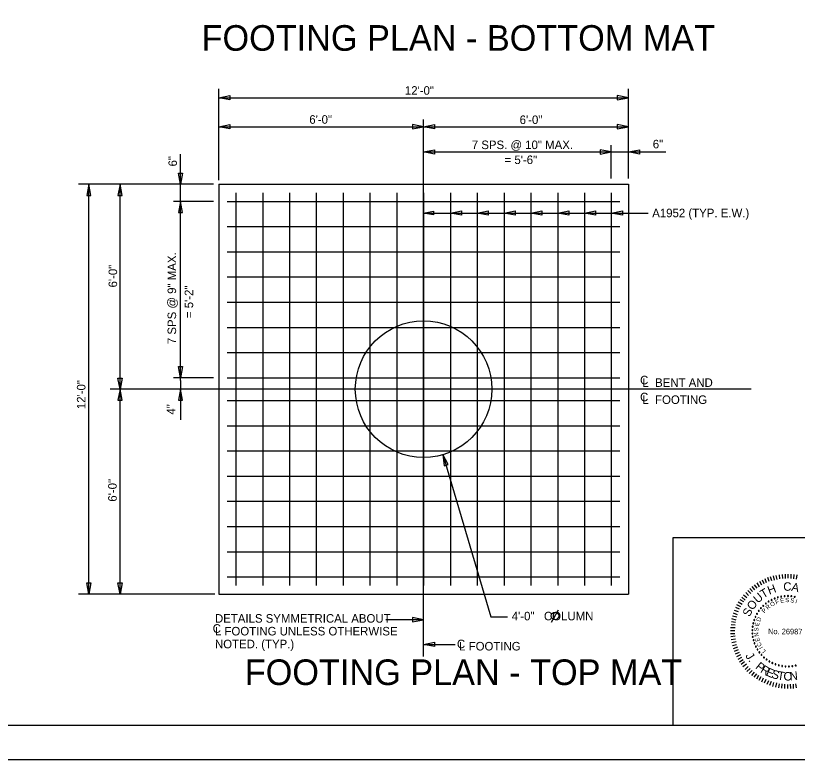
# Model space of a CAD drawing. Extents: x 1970675.2 to 1970711.3, y 796145.2 to 796167.2.
# Drawn here: x 1970688.24 to 1970699.69, y 796145.25 to 796156.14 of the extents above; entities that cross this region are included whole.
import ezdxf

# ---------------------------------------------------------------- set-up
doc = ezdxf.new("R2010")
doc.units = 0
for name, color, linetype in [('BR_AUTO DIMENSION', 7, 'Continuous'), ('BR_BORDER LINES', 7, 'Continuous'), ('BR_CENTER LINES', 7, 'Continuous'), ('BR_CONCRETE', 7, 'Continuous'), ('BR_REBAR', 7, 'Continuous'), ('BR_TEXT', 7, 'Continuous'), ('Level 31', 7, 'Continuous')]:
    doc.layers.add(name, color=color, linetype=linetype)

msp = doc.modelspace()

# ---------------------------------------------------------------- linework, layer by layer
at = {"layer": 'BR_AUTO DIMENSION'}
for p, q in [((1970691.212, 796153.727), (1970691.212, 796155.064)), ((1970697.212, 796153.753), (1970697.212, 796155.064)), ((1970691.212, 796154.935), (1970697.212, 796154.935)), ((1970691.212, 796154.511), (1970694.212, 796154.511)), ((1970694.212, 796154.511), (1970697.212, 796154.511)), ((1970696.962, 796153.753), (1970696.962, 796154.239)), ((1970690.652, 796153.182), (1970690.652, 796154.11)), ((1970694.212, 796154.142), (1970697.761, 796154.142)), ((1970691.134, 796153.667), (1970689.155, 796153.667)), ((1970689.308, 796147.667), (1970689.308, 796153.667)), ((1970689.766, 796150.667), (1970689.766, 796153.667)), ((1970691.134, 796153.417), (1970690.551, 796153.417)), ((1970690.652, 796150.792), (1970690.652, 796153.417)), ((1970694.212, 796153.246), (1970697.5, 796153.246)), ((1970691.134, 796150.834), (1970690.551, 796150.834)), ((1970690.652, 796150.792), (1970690.652, 796150.219)), ((1970689.766, 796147.667), (1970689.766, 796150.667)), ((1970694.496, 796149.709), (1970695.199, 796147.333)), ((1970691.152, 796147.667), (1970689.155, 796147.667)), ((1970695.199, 796147.333), (1970695.443, 796147.333)), ((1970694.212, 796147.291), (1970693.66, 796147.291)), ((1970694.212, 796146.93), (1970694.673, 796146.93))]:
    msp.add_line(p, q, dxfattribs=at)
for points in [[(1970691.374, 796154.904), (1970691.212, 796154.935), (1970691.374, 796154.966)], [(1970697.049, 796154.904), (1970697.212, 796154.935), (1970697.049, 796154.966)], [(1970691.374, 796154.48), (1970691.212, 796154.511), (1970691.374, 796154.543)], [(1970694.049, 796154.48), (1970694.212, 796154.511), (1970694.049, 796154.543)], [(1970694.374, 796154.48), (1970694.212, 796154.511), (1970694.374, 796154.543)], [(1970697.049, 796154.48), (1970697.212, 796154.511), (1970697.049, 796154.543)], [(1970694.374, 796154.111), (1970694.212, 796154.142), (1970694.374, 796154.173)], [(1970696.799, 796154.111), (1970696.962, 796154.142), (1970696.799, 796154.173)], [(1970697.374, 796154.111), (1970697.212, 796154.142), (1970697.374, 796154.173)], [(1970690.683, 796153.83), (1970690.652, 796153.667), (1970690.62, 796153.83)], [(1970689.339, 796153.505), (1970689.308, 796153.667), (1970689.277, 796153.505)], [(1970689.797, 796153.505), (1970689.766, 796153.667), (1970689.735, 796153.505)], [(1970690.683, 796153.255), (1970690.652, 796153.417), (1970690.62, 796153.255)], [(1970694.358, 796153.218), (1970694.212, 796153.246), (1970694.358, 796153.275)], [(1970694.767, 796153.215), (1970694.605, 796153.246), (1970694.767, 796153.278)], [(1970695.16, 796153.215), (1970694.998, 796153.246), (1970695.16, 796153.278)], [(1970695.553, 796153.215), (1970695.39, 796153.246), (1970695.553, 796153.278)], [(1970695.946, 796153.215), (1970695.783, 796153.246), (1970695.946, 796153.278)], [(1970696.339, 796153.215), (1970696.176, 796153.246), (1970696.339, 796153.278)], [(1970696.731, 796153.215), (1970696.569, 796153.246), (1970696.731, 796153.278)], [(1970697.124, 796153.215), (1970696.962, 796153.246), (1970697.124, 796153.278)], [(1970690.683, 796150.997), (1970690.652, 796150.834), (1970690.62, 796150.997)], [(1970689.797, 796150.83), (1970689.766, 796150.667), (1970689.735, 796150.83)], [(1970689.797, 796150.505), (1970689.766, 796150.667), (1970689.735, 796150.505)], [(1970690.683, 796150.505), (1970690.652, 796150.667), (1970690.62, 796150.505)], [(1970694.572, 796149.562), (1970694.496, 796149.709), (1970694.512, 796149.544)], [(1970689.339, 796147.83), (1970689.308, 796147.667), (1970689.277, 796147.83)], [(1970689.797, 796147.83), (1970689.766, 796147.667), (1970689.735, 796147.83)], [(1970694.049, 796147.26), (1970694.212, 796147.291), (1970694.049, 796147.322)], [(1970694.374, 796146.899), (1970694.212, 796146.93), (1970694.374, 796146.961)]]:
    msp.add_lwpolyline(points, close=True, dxfattribs=at)
at = {"layer": 'BR_BORDER LINES'}
for p, q in [((1970697.87, 796148.496), (1970703.236, 796148.496)), ((1970697.87, 796145.746), (1970697.87, 796148.496)), ((1970677.07, 796145.746), (1970710.736, 796145.746))]:
    msp.add_line(p, q, dxfattribs=at)
at = {"layer": 'BR_CENTER LINES'}
for p, q in [((1970694.212, 796146.752), (1970694.212, 796154.617)), ((1970699.009, 796150.667), (1970689.62, 796150.667))]:
    msp.add_line(p, q, dxfattribs=at)
at = {"layer": 'BR_CONCRETE'}
for p, q in [((1970691.212, 796153.667), (1970697.212, 796153.667)), ((1970691.212, 796153.667), (1970691.212, 796147.667)), ((1970697.212, 796153.667), (1970697.212, 796147.667)), ((1970691.212, 796147.667), (1970697.212, 796147.667))]:
    msp.add_line(p, q, dxfattribs=at)
msp.add_circle((1970694.212, 796150.667), 1, dxfattribs=at)
at = {"layer": 'BR_REBAR'}
for p, q in [((1970691.462, 796153.542), (1970691.462, 796147.792)), ((1970691.855, 796153.542), (1970691.855, 796147.792)), ((1970692.248, 796153.542), (1970692.248, 796147.792)), ((1970692.64, 796153.542), (1970692.64, 796147.792)), ((1970693.033, 796153.542), (1970693.033, 796147.792)), ((1970693.426, 796153.542), (1970693.426, 796147.792)), ((1970693.819, 796153.542), (1970693.819, 796147.792)), ((1970694.212, 796153.542), (1970694.212, 796147.792)), ((1970694.605, 796153.542), (1970694.605, 796147.792)), ((1970694.998, 796153.542), (1970694.998, 796147.792)), ((1970695.39, 796153.542), (1970695.39, 796147.792)), ((1970695.783, 796153.542), (1970695.783, 796147.792)), ((1970696.176, 796153.542), (1970696.176, 796147.792)), ((1970696.569, 796153.542), (1970696.569, 796147.792)), ((1970696.962, 796153.542), (1970696.962, 796147.792)), ((1970691.337, 796153.417), (1970697.087, 796153.417)), ((1970691.337, 796153.048), (1970697.087, 796153.048)), ((1970691.337, 796152.679), (1970697.087, 796152.679)), ((1970691.337, 796152.31), (1970697.087, 796152.31)), ((1970691.337, 796151.941), (1970697.087, 796151.941)), ((1970691.337, 796151.572), (1970697.087, 796151.572)), ((1970691.337, 796151.203), (1970697.087, 796151.203)), ((1970691.337, 796150.834), (1970697.087, 796150.834)), ((1970691.337, 796150.501), (1970697.087, 796150.501)), ((1970691.337, 796150.132), (1970697.087, 796150.132)), ((1970691.337, 796149.763), (1970697.087, 796149.763)), ((1970691.337, 796149.394), (1970697.087, 796149.394)), ((1970691.337, 796149.025), (1970697.087, 796149.025)), ((1970691.337, 796148.656), (1970697.087, 796148.656)), ((1970691.337, 796148.287), (1970697.087, 796148.287)), ((1970691.337, 796147.917), (1970697.087, 796147.917))]:
    msp.add_line(p, q, dxfattribs=at)
at = {"layer": 'BR_TEXT'}
for p, q in [((1970699.237, 796147.833), (1970699.213, 796147.889)), ((1970699.275, 796147.85), (1970699.255, 796147.908)), ((1970699.315, 796147.862), (1970699.293, 796147.92)), ((1970699.351, 796147.872), (1970699.338, 796147.933)), ((1970699.392, 796147.882), (1970699.378, 796147.941)), ((1970699.432, 796147.889), (1970699.423, 796147.95)), ((1970699.472, 796147.893), (1970699.468, 796147.954)), ((1970699.511, 796147.896), (1970699.512, 796147.96)), ((1970699.553, 796147.898), (1970699.554, 796147.96)), ((1970699.595, 796147.895), (1970699.597, 796147.959)), ((1970699.635, 796147.892), (1970699.64, 796147.953)), ((1970699.674, 796147.887), (1970699.685, 796147.948)), ((1970699.065, 796147.728), (1970699.025, 796147.778)), ((1970699.099, 796147.753), (1970699.06, 796147.804)), ((1970699.13, 796147.774), (1970699.099, 796147.829)), ((1970699.165, 796147.798), (1970699.135, 796147.852)), ((1970699.2, 796147.816), (1970699.174, 796147.872)), ((1970698.973, 796147.645), (1970698.93, 796147.688)), ((1970699.003, 796147.676), (1970698.959, 796147.72)), ((1970699.032, 796147.703), (1970698.991, 796147.748)), ((1970698.876, 796147.515), (1970698.822, 796147.547)), ((1970698.901, 796147.551), (1970698.847, 796147.584)), ((1970698.922, 796147.58), (1970698.873, 796147.62)), ((1970698.948, 796147.614), (1970698.899, 796147.653)), ((1970696.084, 796147.256), (1970696.189, 796147.438)), ((1970698.824, 796147.405), (1970698.766, 796147.427)), ((1970698.841, 796147.444), (1970698.784, 796147.469)), ((1970698.859, 796147.481), (1970698.802, 796147.508)), ((1970698.799, 796147.329), (1970698.738, 796147.344)), ((1970698.812, 796147.365), (1970698.75, 796147.388)), ((1970698.777, 796147.21), (1970698.715, 796147.217)), ((1970698.781, 796147.251), (1970698.721, 796147.259)), ((1970698.792, 796147.287), (1970698.729, 796147.303)), ((1970698.774, 796147.171), (1970698.709, 796147.171)), ((1970698.772, 796147.129), (1970698.709, 796147.13)), ((1970698.773, 796147.086), (1970698.709, 796147.085)), ((1970698.775, 796147.048), (1970698.714, 796147.041)), ((1970698.779, 796147.007), (1970698.718, 796146.998)), ((1970698.789, 796146.967), (1970698.727, 796146.954)), ((1970698.796, 796146.925), (1970698.735, 796146.911)), ((1970698.808, 796146.888), (1970698.746, 796146.867)), ((1970698.819, 796146.849), (1970698.761, 796146.828)), ((1970698.836, 796146.812), (1970698.778, 796146.785)), ((1970698.853, 796146.776), (1970698.796, 796146.746)), ((1970698.87, 796146.739), (1970698.816, 796146.708)), ((1970698.894, 796146.702), (1970698.839, 796146.671)), ((1970698.915, 796146.673), (1970698.865, 796146.636)), ((1970698.94, 796146.639), (1970698.89, 796146.6)), ((1970698.965, 796146.605), (1970698.921, 796146.564)), ((1970698.994, 796146.579), (1970698.949, 796146.534)), ((1970699.023, 796146.549), (1970698.98, 796146.503)), ((1970699.055, 796146.523), (1970699.014, 796146.476)), ((1970699.088, 796146.497), (1970699.049, 796146.449)), ((1970699.119, 796146.475), (1970699.088, 796146.423)), ((1970699.154, 796146.453), (1970699.123, 796146.399)), ((1970699.188, 796146.433), (1970699.161, 796146.377)), ((1970699.225, 796146.415), (1970699.201, 796146.36)), ((1970699.263, 796146.398), (1970699.242, 796146.341)), ((1970699.303, 796146.385), (1970699.28, 796146.327)), ((1970699.339, 796146.373), (1970699.325, 796146.314)), ((1970699.38, 796146.366), (1970699.365, 796146.304)), ((1970699.419, 796146.354), (1970699.409, 796146.296)), ((1970699.459, 796146.35), (1970699.454, 796146.288)), ((1970699.498, 796146.347), (1970699.498, 796146.285)), ((1970699.54, 796146.344), (1970699.54, 796146.283)), ((1970699.582, 796146.346), (1970699.584, 796146.284)), ((1970699.623, 796146.348), (1970699.626, 796146.286)), ((1970699.661, 796146.352), (1970699.671, 796146.294))]:
    msp.add_line(p, q, dxfattribs=at)
msp.add_circle((1970696.137, 796147.347), 0.055, dxfattribs=at)
for centre, start, end in [((1970699.265, 796147.557), 32.7576, 212.7576), ((1970699.265, 796147.557), 212.7576, 32.7576), ((1970699.309, 796147.581), 27.2191, 207.2191), ((1970699.309, 796147.581), 207.2191, 27.2191), ((1970699.354, 796147.602), 21.6807, 201.6807), ((1970699.354, 796147.602), 201.6807, 21.6807), ((1970699.401, 796147.618), 16.1422, 196.1422), ((1970699.401, 796147.618), 196.1422, 16.1422), ((1970699.45, 796147.629), 10.6038, 190.6038), ((1970699.45, 796147.629), 190.6038, 10.6038), ((1970699.499, 796147.636), 5.0653, 185.0653), ((1970699.499, 796147.636), 185.0653, 5.0653), ((1970699.549, 796147.638), 359.5268, 179.5268), ((1970699.549, 796147.638), 179.5268, 359.5268), ((1970699.599, 796147.635), 353.9884, 173.9884), ((1970699.599, 796147.635), 173.9884, 353.9884), ((1970699.648, 796147.627), 348.4499, 168.4499), ((1970699.648, 796147.627), 168.4499, 348.4499), ((1970699.153, 796147.459), 49.373, 229.373), ((1970699.153, 796147.459), 229.373, 49.373), ((1970699.187, 796147.495), 43.8345, 223.8345), ((1970699.187, 796147.495), 223.8345, 43.8345), ((1970699.225, 796147.528), 38.2961, 218.2961), ((1970699.225, 796147.528), 218.2961, 38.2961), ((1970699.073, 796147.333), 65.9884, 245.9884), ((1970699.073, 796147.333), 245.9884, 65.9884), ((1970699.095, 796147.378), 60.4499, 240.4499), ((1970699.095, 796147.378), 240.4499, 60.4499), ((1970699.122, 796147.42), 54.9114, 234.9114), ((1970699.122, 796147.42), 234.9114, 54.9114), ((1970699.041, 796147.239), 77.0653, 257.0653), ((1970699.041, 796147.239), 257.0653, 77.0653), ((1970699.055, 796147.287), 71.5268, 251.5268), ((1970699.055, 796147.287), 251.5268, 71.5268), ((1970699.028, 796147.14), 88.1422, 268.1422), ((1970699.029, 796147.09), 93.6807, 273.6807), ((1970699.032, 796147.19), 82.6038, 262.6038), ((1970699.028, 796147.14), 268.1422, 88.1422), ((1970699.029, 796147.09), 273.6807, 93.6807), ((1970699.032, 796147.19), 262.6038, 82.6038), ((1970699.034, 796147.041), 99.2191, 279.2191), ((1970699.034, 796147.041), 279.2191, 99.2191), ((1970699.045, 796146.992), 104.7576, 284.7576), ((1970699.045, 796146.992), 284.7576, 104.7576), ((1970699.059, 796146.944), 110.2961, 290.2961), ((1970699.059, 796146.944), 290.2961, 110.2961), ((1970699.079, 796146.898), 115.8345, 295.8345), ((1970699.079, 796146.898), 295.8345, 115.8345), ((1970699.103, 796146.855), 121.373, 301.373), ((1970699.103, 796146.855), 301.373, 121.373), ((1970699.131, 796146.813), 126.9114, 306.9114), ((1970699.131, 796146.813), 306.9114, 126.9114), ((1970699.162, 796146.775), 132.4499, 312.4499), ((1970699.162, 796146.775), 312.4499, 132.4499), ((1970699.198, 796146.74), 137.9884, 317.9884), ((1970699.198, 796146.74), 317.9884, 137.9884), ((1970699.236, 796146.708), 143.5268, 323.5268), ((1970699.236, 796146.708), 323.5268, 143.5268), ((1970699.278, 796146.68), 149.0653, 329.0653), ((1970699.278, 796146.68), 329.0653, 149.0653), ((1970699.321, 796146.657), 154.6038, 334.6038), ((1970699.321, 796146.657), 334.6038, 154.6038), ((1970699.367, 796146.638), 160.1422, 340.1422), ((1970699.367, 796146.638), 340.1422, 160.1422), ((1970699.415, 796146.623), 345.6807, 165.6807), ((1970699.662, 796146.62), 13.373, 193.373), ((1970699.415, 796146.623), 165.6807, 345.6807), ((1970699.464, 796146.613), 351.2191, 171.2191), ((1970699.464, 796146.613), 171.2191, 351.2191), ((1970699.513, 796146.607), 356.7576, 176.7576), ((1970699.513, 796146.607), 176.7576, 356.7576), ((1970699.563, 796146.607), 2.2961, 182.2961), ((1970699.563, 796146.607), 182.2961, 2.2961), ((1970699.613, 796146.611), 7.8345, 187.8345), ((1970699.613, 796146.611), 187.8345, 7.8345), ((1970699.662, 796146.62), 193.373, 13.373)]:
    msp.add_arc(centre, 0.00701, start, end, dxfattribs=at)
at = {"layer": 'Level 31'}
msp.add_lwpolyline([(1970675.236, 796167.246), (1970675.236, 796145.246), (1970711.236, 796145.246), (1970711.236, 796167.246)], dxfattribs=at)

# ---------------------------------------------------------------- texts
at = {"layer": 'BR_AUTO DIMENSION'}
for s, p in [('12\'-0"', (1970693.938, 796154.979)), ('6\'-0"', (1970692.538, 796154.554)), ('6\'-0"', (1970695.619, 796154.55)), ('C', (1970697.383, 796150.738)), ('C', (1970697.383, 796150.49)), ('C', (1970691.123, 796147.1)), ('C', (1970694.7, 796146.874))]:
    msp.add_text(s, height=0.125, dxfattribs=at).set_placement(p)
for s, p in [('6\'-0"', (1970689.723, 796152.157)), ('12\'-0"', (1970689.259, 796150.375)), ('6\'-0"', (1970689.717, 796149.02))]:
    msp.add_text(s, height=0.125, rotation=90, dxfattribs=at).set_placement(p)
at = {"layer": 'BR_TEXT'}
for s, height, p in [('FOOTING PLAN - BOTTOM MAT', 0.375, (1970690.96, 796155.623)), ('6"', 0.125, (1970697.569, 796154.194)), ('A1952 (TYP. E.W.)', 0.125, (1970697.561, 796153.185)), ('L  BENT AND', 0.125, (1970697.417, 796150.701)), ('L  FOOTING', 0.125, (1970697.417, 796150.451)), ('DETAILS SYMMETRICAL ABOUT ', 0.125, (1970691.156, 796147.248)), ('4\'-0"   COLUMN', 0.125, (1970695.503, 796147.282)), ('L FOOTING UNLESS OTHERWISE', 0.125, (1970691.156, 796147.061)), ('NOTED. (TYP.)', 0.125, (1970691.156, 796146.873)), ('L FOOTING', 0.125, (1970694.733, 796146.841)), ('FOOTING PLAN - TOP MAT', 0.375, (1970691.593, 796146.335))]:
    msp.add_text(s, height=height, dxfattribs=at).set_placement(p)
for s, height, rotation, p in [('7 SPS. @ 10" MAX.', 0.125, 360, (1970694.918, 796154.183)), ('6"', 0.125, 90, (1970690.6, 796153.929)), ('= 5\'-6"', 0.125, 360, (1970695.398, 796153.964)), ('7 SPS @ 9" MAX.', 0.125, 90, (1970690.587, 796151.327)), ('= 5\'-2"', 0.125, 90, (1970690.837, 796151.708)), ('4"', 0.125, 90, (1970690.576, 796150.294)), ('H', 0.124, 20.3637, (1970699.276, 796147.657)), ('C', 0.124, 359.5482, (1970699.48, 796147.716)), ('A', 0.124, 348.1981, (1970699.592, 796147.716)), ('U', 0.124, 40.8022, (1970699.107, 796147.525)), ('T', 0.124, 30.4992, (1970699.188, 796147.6)), ('O', 0.124, 52.0267, (1970699.032, 796147.421)), ('O', 0.0622, 30.8477, (1970699.31, 796147.478)), ('F', 0.0622, 20.6127, (1970699.377, 796147.514)), ('E', 0.0622, 11.4103, (1970699.442, 796147.536)), ('S', 0.0622, 2.208, (1970699.51, 796147.547)), ('S', 0.0622, 352.6608, (1970699.581, 796147.547)), ('I', 0.0622, 343.1136, (1970699.652, 796147.535)), ('S', 0.124, 63.2511, (1970698.987, 796147.325)), ('P', 0.0622, 49.9421, (1970699.206, 796147.382)), ('R', 0.0622, 40.3949, (1970699.254, 796147.434)), ('D', 0.0622, 69.0364, (1970699.139, 796147.257)), ('E', 0.0622, 78.2388, (1970699.122, 796147.19)), ('S', 0.0622, 87.786, (1970699.116, 796147.119)), ('N', 0.0622, 97.3332, (1970699.122, 796147.048)), ('No. 26987', 0.0817, 359.5268, (1970699.257, 796147.08)), ('E', 0.0622, 106.5355, (1970699.14, 796146.981)), ('C', 0.0622, 116.4266, (1970699.169, 796146.914)), ('I', 0.0622, 121.1011, (1970699.187, 796146.884)), ('L', 0.0622, 129.9595, (1970699.228, 796146.832)), ('J', 0.124, 302.9559, (1970698.92, 796146.763)), ('.', 0.124, 309.3974, (1970698.964, 796146.695)), ('P', 0.124, 321.1035, (1970699.063, 796146.586)), ('R', 0.124, 328.5359, (1970699.136, 796146.528)), ('E', 0.124, 335.9684, (1970699.216, 796146.48)), ('S', 0.124, 343.0292, (1970699.297, 796146.444)), ('T', 0.124, 350.4617, (1970699.387, 796146.418)), ('O', 0.124, 358.1419, (1970699.482, 796146.403)), ('N', 0.124, 5.8221, (1970699.579, 796146.401))]:
    msp.add_text(s, height=height, rotation=rotation, dxfattribs=at).set_placement(p)

doc.saveas('drawing.dxf')
